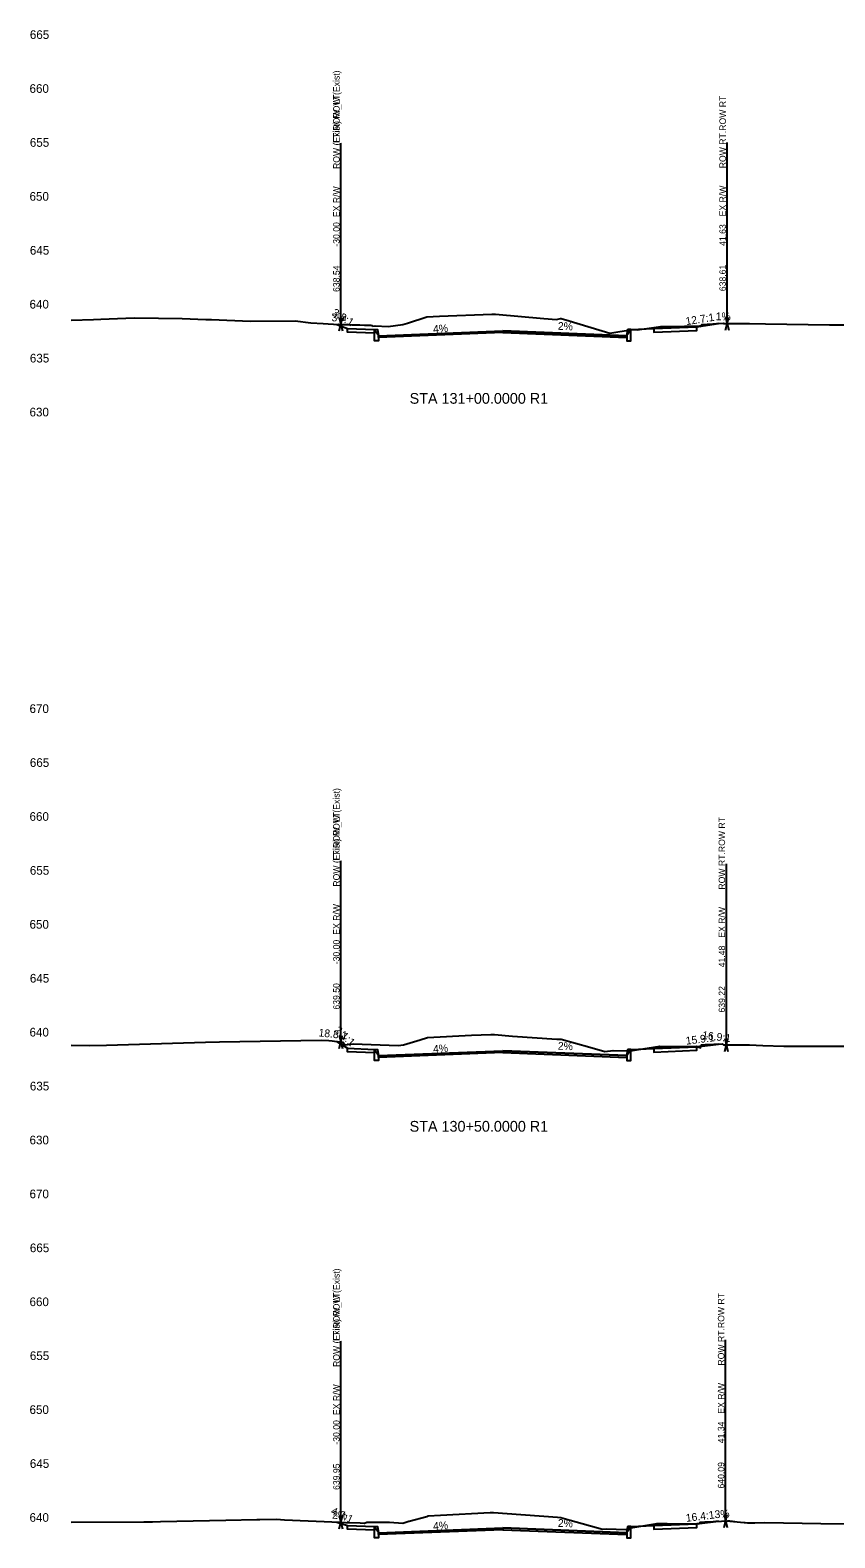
# Model space of a CAD drawing. Extents: x 2 to 741, y 16 to 2207.
# Drawn here: x 442.4 to 591.6, y 272 to 551.6 of the extents above; entities that cross this region are included whole.
import ezdxf

# ---------------------------------------------------------------- set-up
doc = ezdxf.new("R2010")
doc.units = 0
for name, color, linetype in [('Draft_XS_Feature_Name', 7, 'Continuous'), ('Draft_XS_Label', 7, 'Continuous'), ('Draft_XS_Point_Label_Indicator', 7, 'Continuous'), ('Draft_XS_Terminator', 7, 'Continuous'), ('Draft_XS_Text', 7, 'Continuous'), ('E_ROW', 7, 'Continuous'), ('E_Terrain_Exterior', 7, 'Continuous'), ('E_Terrain_Points_Low', 7, 'Continuous'), ('Grade_Veg_Grass', 7, 'Continuous'), ('P_XS_Sections', 7, 'Continuous'), ('Road_Curb', 7, 'Continuous'), ('Road_Pave_Asphalt', 7, 'Continuous'), ('Road_Sidewalk', 7, 'Continuous'), ('Terrain_Design', 7, 'Continuous')]:
    doc.layers.add(name, color=color, linetype=linetype)

msp = doc.modelspace()

# ---------------------------------------------------------------- linework, layer by layer
at = {"layer": 'Draft_XS_Terminator'}
for p, q in [((500, 497.08), (500, 519.08)), ((500, 497.08), (500, 519.08)), ((571.63, 497.22), (571.63, 519.22)), ((500, 363.99), (500, 385.99)), ((500, 363.99), (500, 385.99)), ((571.48, 363.44), (571.48, 385.44)), ((500, 274.91), (500, 296.91)), ((500, 274.91), (500, 296.91)), ((571.34, 275.17), (571.34, 297.17))]:
    msp.add_line(p, q, dxfattribs=at)
at = {"layer": 'E_ROW'}
for p, q in [((500, 497.08), (500, 530.68)), ((500, 497.08), (500, 530.68)), ((571.63, 497.22), (571.63, 530.82)), ((499.7, 495.88), (500.3, 498.28)), ((499.7, 498.28), (500.3, 495.88)), ((499.7, 495.88), (500.3, 498.28)), ((499.7, 498.28), (500.3, 495.88)), ((571.33, 496.02), (571.93, 498.42)), ((571.33, 498.42), (571.93, 496.02)), ((500, 363.99), (500, 397.59)), ((500, 363.99), (500, 397.59)), ((571.48, 363.44), (571.48, 397.04)), ((499.7, 362.79), (500.3, 365.19)), ((499.7, 365.19), (500.3, 362.79)), ((499.7, 362.79), (500.3, 365.19)), ((499.7, 365.19), (500.3, 362.79)), ((571.18, 362.24), (571.78, 364.64)), ((571.18, 364.64), (571.78, 362.24)), ((500, 274.91), (500, 308.51)), ((500, 274.91), (500, 308.51)), ((571.34, 275.17), (571.34, 308.77)), ((499.7, 273.71), (500.3, 276.11)), ((499.7, 276.11), (500.3, 273.71)), ((499.7, 273.71), (500.3, 276.11)), ((499.7, 276.11), (500.3, 273.71)), ((571.04, 273.97), (571.64, 276.37)), ((571.04, 276.37), (571.64, 273.97))]:
    msp.add_line(p, q, dxfattribs=at)
at = {"layer": 'E_Terrain_Exterior'}
for points in [[(450, 497.87), (454.14, 498), (455.46, 498.04), (461.69, 498.25), (466.16, 498.21), (470.57, 498.17), (474.94, 498), (476.02, 497.96), (483.18, 497.69), (491.5, 497.72), (494.4, 497.35), (496.73, 497.24), (499.57, 497.02), (499.58, 497.1), (499.59, 497.12), (499.59, 497.13), (499.59, 497.13), (499.59, 497.13), (499.59, 497.13), (499.59, 497.13), (500.08, 497.07), (500.71, 497.05), (501.25, 497.03), (501.27, 497.03), (501.67, 497.02), (502.03, 497.01), (502.06, 497.01), (502.15, 497), (503.49, 496.96), (504.35, 496.93), (504.5, 496.92), (504.65, 496.92), (505.15, 496.9), (505.51, 496.89), (505.59, 496.89), (505.68, 496.88), (505.81, 496.88), (505.89, 496.72), (506.35, 496.78), (508.74, 496.7), (511.47, 497.05), (512.36, 497.31), (515.95, 498.49), (518.27, 498.61), (527.97, 498.93), (528.22, 498.93), (528.35, 498.93), (528.65, 498.93), (537.62, 498.16), (539.98, 497.99), (540.69, 498.14), (540.83, 498.13), (542.35, 497.71), (549.85, 495.42), (553.99, 496.09), (554.92, 496.06), (558.04, 496.48), (559.3, 496.68), (560.91, 496.67), (566.52, 496.78), (566.75, 496.7), (566.78, 496.85), (566.94, 497.04), (569.97, 497.24), (570.92, 497.28), (570.97, 497.22), (572.31, 497.22), (572.46, 497.22), (572.56, 497.22), (572.64, 497.22), (572.68, 497.22), (572.79, 497.22), (572.92, 497.22), (573.25, 497.22), (573.48, 497.22), (573.75, 497.22), (574.45, 497.22), (575.63, 497.22), (575.76, 497.22), (578.75, 497.18), (590.59, 496.99), (596.14, 497)], [(450, 363.4), (453.39, 363.35), (456.55, 363.41), (474.87, 363.93), (477.48, 363.99), (496.35, 364.32), (497.76, 364.29), (498.4, 364.2), (499.74, 364), (499.9, 364), (500.38, 363.98), (500.66, 363.44), (502.25, 363.62), (510.62, 363.34), (511.63, 363.47), (514.72, 364.36), (516.06, 364.8), (524.21, 365.24), (527.81, 365.36), (527.91, 365.36), (528.35, 365.36), (528.47, 365.36), (531.8, 365.07), (540.07, 364.48), (540.33, 364.53), (540.84, 364.49), (546.17, 363.03), (548.94, 362.19), (550.47, 362.43), (553.68, 362.34), (554.84, 362.5), (559.12, 363.19), (564.63, 363.15), (565.93, 363.18), (566.71, 362.93), (566.82, 363.41), (566.85, 363.46), (567.53, 363.5), (570.77, 363.65), (570.94, 363.44), (575.53, 363.44), (575.54, 363.44), (575.54, 363.44), (575.54, 363.44), (575.54, 363.44), (575.54, 363.44), (575.54, 363.44), (575.54, 363.44), (575.54, 363.44), (575.74, 363.43), (578.24, 363.35), (582.11, 363.22), (582.2, 363.22), (582.28, 363.21), (602.69, 363.23)], [(450, 274.95), (463.45, 274.97), (465.03, 275), (466.57, 275.03), (478.68, 275.3), (484.38, 275.43), (484.94, 275.44), (488.05, 275.51), (489.52, 275.37), (499.81, 274.91), (500.87, 274.88), (503.57, 274.78), (504.34, 274.76), (504.4, 274.76), (504.8, 274.96), (509, 274.96), (511.46, 274.72), (512.6, 275.11), (512.66, 275.09), (515.91, 275.99), (516.15, 276.1), (518.48, 276.2), (527.68, 276.7), (527.92, 276.71), (528.01, 276.71), (528.06, 276.72), (528.32, 276.7), (530.84, 276.51), (540.16, 275.84), (540.74, 275.79), (540.81, 275.82), (542.51, 275.29), (548.49, 273.65), (549.23, 273.67), (552.82, 273.57), (553.78, 273.89), (558.58, 274.66), (560.48, 274.71), (566.4, 274.63), (566.46, 274.67), (566.65, 274.93), (567.47, 275), (570.58, 275.12), (571.68, 275.2), (571.72, 275.19), (571.78, 275.18), (571.82, 275.18), (571.84, 275.18), (571.87, 275.18), (571.98, 275.16), (572.08, 275.15), (572.2, 275.14), (572.37, 275.12), (572.58, 275.1), (572.79, 275.08), (573.04, 275.06), (573.48, 275.01), (574.12, 274.95), (574.79, 274.88), (574.96, 274.86), (575.41, 274.81), (576.77, 274.82), (578.61, 274.87), (589.02, 274.69), (595.46, 274.63)]]:
    msp.add_lwpolyline(points, dxfattribs=at)
at = {"layer": 'Grade_Veg_Grass'}
for points in [[(499.25, 497.05), (501.25, 496.32), (501.25, 496.32)], [(553.75, 496.12), (558, 496.29)], [(570, 497.24), (566, 496.61), (566, 496.61)], [(499.25, 364.07), (501.25, 362.82), (501.25, 362.82)], [(570, 363.61), (566, 363.11), (566, 363.11)], [(553.75, 362.62), (558, 362.79)], [(499.25, 274.94), (501.25, 274.32), (501.25, 274.32)], [(553.75, 274.12), (558, 274.29)], [(570, 275.1), (566, 274.61), (566, 274.61)]]:
    msp.add_lwpolyline(points, dxfattribs=at)
at = {"layer": 'Road_Curb'}
for points in [[(507, 494.95), (507, 494.04), (506.25, 494.04), (506.25, 496.12), (506.77, 496.12), (507, 494.95)], [(553, 494.95), (553, 494.04), (553.75, 494.04), (553.75, 496.12), (553.23, 496.12), (553, 494.95)], [(507, 361.45), (507, 360.54), (506.25, 360.54), (506.25, 362.62), (506.77, 362.62), (507, 361.45)], [(553, 361.45), (553, 360.54), (553.75, 360.54), (553.75, 362.62), (553.23, 362.62), (553, 361.45)], [(507, 272.95), (507, 272.04), (506.25, 272.04), (506.25, 274.12), (506.77, 274.12), (507, 272.95)], [(553, 272.95), (553, 272.04), (553.75, 272.04), (553.75, 274.12), (553.23, 274.12), (553, 272.95)]]:
    msp.add_lwpolyline(points, dxfattribs=at)
at = {"layer": 'Road_Pave_Asphalt'}
for points in [[(530, 495.87), (530, 495.54), (507, 494.62), (507, 494.95), (530, 495.87)], [(530, 495.87), (530, 495.54), (553, 494.62), (553, 494.95), (530, 495.87)], [(530, 362.37), (530, 362.04), (507, 361.12), (507, 361.45), (530, 362.37)], [(530, 362.37), (530, 362.04), (553, 361.12), (553, 361.45), (530, 362.37)], [(530, 273.87), (530, 273.54), (507, 272.62), (507, 272.95), (530, 273.87)], [(530, 273.87), (530, 273.54), (553, 272.62), (553, 272.95), (530, 273.87)]]:
    msp.add_lwpolyline(points, dxfattribs=at)
at = {"layer": 'Road_Sidewalk'}
for points in [[(506.25, 496.12), (506.25, 495.45), (501.25, 495.65), (501.25, 496.32), (506.25, 496.12)], [(558, 496.29), (558, 495.62), (566, 495.94), (566, 496.61), (558, 496.29)], [(506.25, 362.62), (506.25, 361.95), (501.25, 362.15), (501.25, 362.82), (506.25, 362.62)], [(558, 362.79), (558, 362.12), (566, 362.44), (566, 363.11), (558, 362.79)], [(506.25, 274.12), (506.25, 273.45), (501.25, 273.65), (501.25, 274.32), (506.25, 274.12)], [(558, 274.29), (558, 273.62), (566, 273.94), (566, 274.61), (558, 274.29)]]:
    msp.add_lwpolyline(points, dxfattribs=at)
at = {"layer": 'Terrain_Design'}
for points in [[(499.25, 497.05), (501.25, 496.32), (506.25, 496.12), (506.77, 496.12), (507, 494.95), (530, 495.87), (553, 494.95), (553.23, 496.12), (553.75, 496.12), (558, 496.29), (566, 496.61), (570, 497.24)], [(499.25, 497.05), (501.25, 496.32), (506.25, 496.12), (506.77, 495.31), (507, 494.95), (530, 495.87), (553, 494.95), (553.23, 495.31), (553.75, 496.12), (558, 496.29), (566, 496.61), (570, 497.24)], [(499.25, 364.07), (501.25, 362.82), (506.25, 362.62), (506.77, 362.62), (507, 361.45), (530, 362.37), (553, 361.45), (553.23, 362.62), (553.75, 362.62), (558, 362.79), (566, 363.11), (570, 363.61)], [(499.25, 364.07), (501.25, 362.82), (506.25, 362.62), (506.77, 361.81), (507, 361.45), (530, 362.37), (553, 361.45), (553.23, 361.81), (553.75, 362.62), (558, 362.79), (566, 363.11), (570, 363.61)], [(499.25, 274.94), (501.25, 274.32), (506.25, 274.12), (506.77, 274.12), (507, 272.95), (530, 273.87), (553, 272.95), (553.23, 274.12), (553.75, 274.12), (558, 274.29), (566, 274.61), (570, 275.1)], [(499.25, 274.94), (501.25, 274.32), (506.25, 274.12), (506.77, 273.31), (507, 272.95), (530, 273.87), (553, 272.95), (553.23, 273.31), (553.75, 274.12), (558, 274.29), (566, 274.61), (570, 275.1)]]:
    msp.add_lwpolyline(points, dxfattribs=at)

# ---------------------------------------------------------------- texts
at = {"layer": 'Draft_XS_Feature_Name'}
for s, p in [('ROW (Exist).ROW (Exist)', (499.76, 525.88)), ('ROW_LT.ROW_LT', (499.76, 525.88)), ('ROW RT.ROW RT', (571.39, 526.02)), ('ROW (Exist).ROW (Exist)', (499.76, 392.79)), ('ROW_LT.ROW_LT', (499.76, 392.79)), ('ROW RT.ROW RT', (571.24, 392.24)), ('ROW (Exist).ROW (Exist)', (499.76, 303.71)), ('ROW_LT.ROW_LT', (499.76, 303.71)), ('ROW RT.ROW RT', (571.1, 303.97))]:
    msp.add_text(s, height=1.2, rotation=90, dxfattribs=at).set_placement(p)
at = {"layer": 'Draft_XS_Label'}
for s, p in [('-30.00', (499.76, 511.48)), ('-30.00', (499.76, 511.48)), ('41.63', (571.39, 511.62)), ('638.54', (499.76, 503.08)), ('638.54', (499.76, 503.08)), ('638.61', (571.39, 503.22)), ('-30.00', (499.76, 378.39)), ('-30.00', (499.76, 378.39)), ('41.48', (571.24, 377.84)), ('639.50', (499.76, 369.99)), ('639.50', (499.76, 369.99)), ('639.22', (571.24, 369.44)), ('-30.00', (499.76, 289.31)), ('-30.00', (499.76, 289.31)), ('41.34', (571.1, 289.57)), ('639.95', (499.76, 280.91)), ('639.95', (499.76, 280.91)), ('640.09', (571.1, 281.17))]:
    msp.add_text(s, height=1.2, rotation=90, dxfattribs=at).set_placement(p)
at = {"layer": 'Draft_XS_Point_Label_Indicator'}
for p in [(499.24, 497.03), (501.24, 496.31), (506.24, 496.11), (506.76, 496.11), (506.99, 494.94), (552.99, 494.94), (553.22, 496.11), (553.74, 496.11), (557.99, 496.28), (565.99, 496.6), (569.99, 497.23), (506.99, 494.02), (552.99, 494.02), (499.24, 364.06), (569.99, 363.6), (501.24, 362.81), (506.24, 362.61), (506.76, 362.61), (506.99, 361.44), (552.99, 361.44), (553.22, 362.61), (553.74, 362.61), (557.99, 362.78), (565.99, 363.1), (506.99, 360.52), (552.99, 360.52), (499.24, 274.93), (501.24, 274.31), (506.24, 274.11), (506.76, 274.11), (553.22, 274.11), (553.74, 274.11), (557.99, 274.28), (565.99, 274.6), (569.99, 275.09), (506.99, 272.94), (506.99, 272.02), (552.99, 272.94), (552.99, 272.02)]:
    msp.add_text('X', height=0.024, dxfattribs=at).set_placement(p)
at = {"layer": 'Draft_XS_Text'}
for s, height, p in [('665', 1.608, (442.32, 550)), ('660', 1.608, (442.26, 540)), ('655', 1.608, (442.32, 530)), ('650', 1.608, (442.26, 520)), ('645', 1.608, (442.32, 510)), ('640', 1.608, (442.26, 500)), ('635', 1.608, (442.32, 490)), ('STA 131+00.0000 R1', 1.992, (512.74, 482.35)), ('630', 1.608, (442.26, 480)), ('670', 1.608, (442.26, 425)), ('665', 1.608, (442.32, 415)), ('660', 1.608, (442.26, 405)), ('655', 1.608, (442.32, 395)), ('650', 1.608, (442.26, 385)), ('645', 1.608, (442.32, 375)), ('640', 1.608, (442.26, 365)), ('635', 1.608, (442.32, 355)), ('STA 130+50.0000 R1', 1.992, (512.74, 347.35)), ('630', 1.608, (442.26, 345)), ('670', 1.608, (442.26, 335)), ('665', 1.608, (442.32, 325)), ('660', 1.608, (442.26, 315)), ('655', 1.608, (442.32, 305)), ('650', 1.608, (442.26, 295)), ('645', 1.608, (442.32, 285)), ('640', 1.608, (442.26, 275))]:
    msp.add_text(s, height=height, dxfattribs=at).set_placement(p)
for s, rotation, p in [('3%', 2.8791, (498.28, 497.6)), ('3.3:1', 328.5812, (498.21, 498.88)), ('12.7:1', 8.9651, (564.04, 496.91)), ('1%', 359.3294, (569.5, 497.85)), ('4%', 4.5657, (517.14, 495.45)), ('2%', 357.7094, (540.21, 496.07)), ('18.8:1', 353.9376, (495.8, 365.04)), ('2.1:1', 316.825, (498.7, 366.03)), ('4%', 4.5657, (517.14, 361.95)), ('2%', 357.7094, (540.21, 362.57)), ('15.9:1', 7.1899, (564.04, 363.47)), ('16.9:1', 353.2698, (566.93, 364.58)), ('4.2:1', 334.7805, (497.99, 276.52)), ('2%', 357.6226, (498.34, 275.58)), ('16.4:1', 6.9494, (564.04, 274.98)), ('3%', 3.2144, (569.32, 275.66)), ('4%', 4.5657, (517.14, 273.45)), ('2%', 357.7094, (540.21, 274.07))]:
    msp.add_text(s, height=1.44, rotation=rotation, dxfattribs=at).set_placement(p)
at = {"layer": 'E_ROW'}
for p in [(499.76, 516.96), (499.76, 516.96), (571.39, 517.1), (499.76, 383.87), (499.76, 383.87), (571.24, 383.32), (499.76, 294.79), (499.76, 294.79), (571.1, 295.05)]:
    msp.add_text('EX R/W', height=1.2, rotation=90, dxfattribs=at).set_placement(p)
at = {"layer": 'E_Terrain_Points_Low'}
for p in [(529.99, 495.86), (529.99, 362.36), (529.99, 273.86)]:
    msp.add_text('X', height=0.024, dxfattribs=at).set_placement(p)
at = {"layer": 'P_XS_Sections'}
for p in [(450, 480), (450, 345)]:
    msp.add_text('-', height=0.0001, dxfattribs=at).set_placement(p)

doc.saveas('drawing.dxf')
